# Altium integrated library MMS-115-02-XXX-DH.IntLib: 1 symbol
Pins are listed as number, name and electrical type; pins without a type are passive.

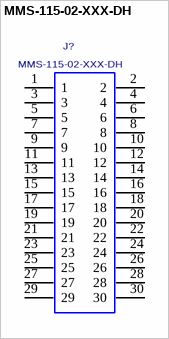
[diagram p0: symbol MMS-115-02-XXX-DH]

## MMS-115-02-XXX-DH
designator J?
2MM SURFACE MOUNT BOX CONNECTOR STRIP ASM, 30 PINS.; MANUFACTURER: SAMTEC
footprint MMS-115-02-XXX-DH
pins: 1, 2, 3, 4, 5, 6, 7, 8, 9, 10, 11, 12, 13, 14, 15, 16, 17, 18, 19, 20, 21, 22, 23, 24, 25, 26, 27, 28, 29, 30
